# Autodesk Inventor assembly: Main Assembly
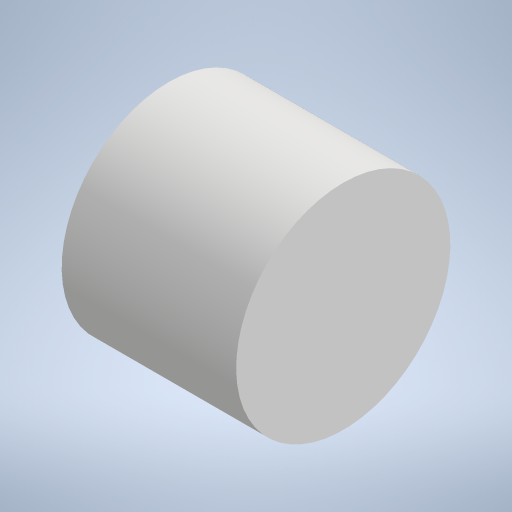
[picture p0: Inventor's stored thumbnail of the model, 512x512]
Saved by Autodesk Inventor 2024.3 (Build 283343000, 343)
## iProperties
Created: 2024-12
Part Number: Main Assembly
Document SubType Name: Assembly
Designer: ruhr
Author: ruhr
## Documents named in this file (2)
- C:\Users\ruhr\OneDrive - Mercantec\Dokumenter\DigiTwinVideo\Main Assembly.iam
- C:\Users\ruhr\OneDrive - Mercantec\Dokumenter\DigiTwinVideo\Part1.ipt
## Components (1 placed, 1 different names)
1. Part1:1
